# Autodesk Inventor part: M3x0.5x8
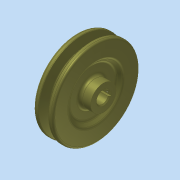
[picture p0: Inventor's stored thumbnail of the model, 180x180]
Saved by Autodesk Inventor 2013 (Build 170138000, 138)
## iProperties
Company: 한국ATC센터
Created: 2009-02
Part Number: M3x0.5x8
Document SubType Name: Modeling
Designer: KYOUNG IL JANG
Density: 7.25 g/cm^3
Mass: 594.654 g
Surface Area: 210.328 cm^2
Volume: 82.0213 cm^3
Material: 주철
Vendor: CBT Solutions
Author: KYOUNG IL JANG
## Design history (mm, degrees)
sketch "스케치1"
  geometry: L1 (-13, 0)-(13, 0); L2 (-13, 0)-(-13, 12.5); L3 (-13, 12.5)-(-9, 12.5); L4 (-9, 12.5)-(-9, 23); L5 (-9, 23)-(-13, 27); L6 (-13, 27)-(-13, 42.7); L7 (-13, 42.7)-(-8.325, 42.7); L8 (-8.325, 42.7)-(-5.574, 33.7); L9 (-5.574, 33.7)-(-1.426, 33.7); L10 (-1.426, 33.7)-(1.325, 42.7); L11 (1.325, 42.7)-(6, 42.7); L12 (6, 42.7)-(6, 27); L13 (6, 27)-(2, 23); L14 (2, 23)-(2, 12.5); L15 (2, 12.5)-(13, 12.5); L16 (13, 12.5)-(13, 0); L17 (-7.5, 40)-(0.5, 40); 2 further points
  constraints: 34 end point, 6 parallel, 5 collinear, 5 equal length, 4 perpendicular, 2 point on line, 1 coincident, 1 horizontal, 1 midpoint
  dimensions: "d0" = 26 distance of L1.start L1.end; "d1" = 2.7 distance between parallel lines of L7 L17; "d2" = 6.3 distance between parallel lines of L9 L17; "d3" = 8 distance of L17.start L17.end; "d4" = 34 deg angle of L10 L8; "d5" = 19 distance between parallel lines of L12 L6; "d7" = 25 diameter of L15 L1; "d8" = 46 diameter of L13.end L1; "d9" = 54 diameter of L12.end L1; "d10" = 4 distance between parallel lines of L2 L4; "d11" = 80 diameter of L17 L1
revolve "회전1" sketch "스케치1" stored, may be unused: angle "d12" = 90 deg
sketch "스케치2"
  geometry: L1 (-2, 5.657)-(-2, 7.8); L2 (-2, 7.8)-(2, 7.8); L3 (2, 7.8)-(2, 5.657); A1 r 6 centre (0, 0) between (-2, 5.657) and (2, 5.657); 1 further point
  constraints: 6 end point, 2 parallel, 2 point on circle, 1 centre point, 1 coincident, 1 perpendicular, 1 vertical
  dimensions: "d13" = 12 diameter of A1; "d14" = 13.8 dimension on A1 L2; "d15" = 4 distance of L1.end L2.end
extrude "돌출1" cut sketch "스케치2" stored distance "d16" = 10; taper "d17" = 0 deg
node "작업 평면1"
sketch "스케치3"
  geometry: L1 (-5.5, 12.5)-(-5.5, -12.5) reference; 3 further points
  constraints: 1 horizontal alignment, 1 midpoint
  dimensions: "d18" = 4 distance from line of point (-1.5, 0) L1
hole "구멍1" sketch "스케치3" at (-1.5, 0) diameter "d19" = 2.459; stored, may be unused: countersink angle "d23" = 90 deg, drill point angle "d25" = 118 deg; dims "d20" = 6, "d21" = 4, "d22" = 2, "d24" = 8
fillet "모깎기1" dims "d26" = 2, "d27" = 0.5, "d28" = 1, "d29" = 3
chamfer "모따기1" distance "d30" = 1; stored, may be unused: second distance "d31" = 2, angle "d32" = 45 deg
node "솔리드1"
